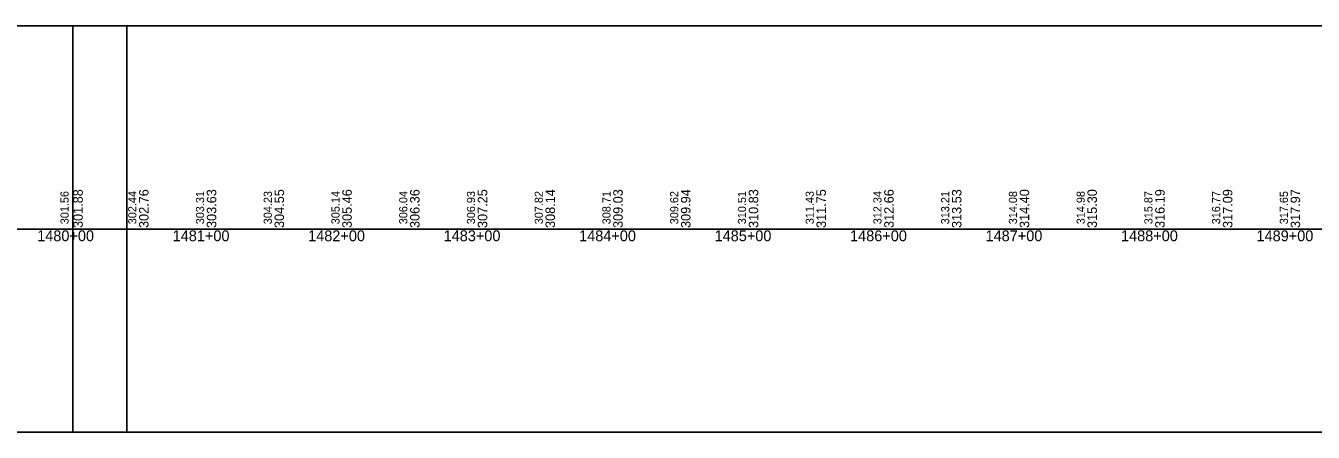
# Model space of a CAD drawing. Extents: x 2898 to 49495, y -15038 to -13538.
# Drawn here: x 37421 to 38371, y -15038 to -14738 of the extents above; entities that cross this region are included whole.
import ezdxf

# ---------------------------------------------------------------- set-up
doc = ezdxf.new("R2010")
doc.units = 0
for name, color, linetype in [('RD_DDB_StaTX', 7, 'Continuous'), ('RD_DDB_StripGrade', 7, 'Continuous'), ('RD_GPK_Profile_Cell', 7, 'Continuous'), ('RD_SHT_ShtClip', 7, 'Continuous')]:
    doc.layers.add(name, color=color, linetype=linetype)

msp = doc.modelspace()

# ---------------------------------------------------------------- linework, layer by layer
at = {"layer": 'RD_GPK_Profile_Cell'}
msp.add_line((2976.05, -14888.47), (48721.13, -14888.47), dxfattribs=at)
at = {"layer": 'RD_SHT_ShtClip'}
for points in [[(35955.38, -14738.47), (37495.38, -14738.47), (37495.38, -15038.47), (35955.38, -15038.47)], [(37455.38, -14738.47), (38995.38, -14738.47), (38995.38, -15038.47), (37455.38, -15038.47)]]:
    msp.add_lwpolyline(points, close=True, dxfattribs=at)

# ---------------------------------------------------------------- texts
at = {"layer": 'RD_DDB_StaTX'}
for s, p in [('1480+00', (37429.18, -14897.47)), ('1481+00', (37529.18, -14897.47)), ('1482+00', (37629.18, -14897.47)), ('1483+00', (37729.18, -14897.47)), ('1484+00', (37829.18, -14897.47)), ('1485+00', (37929.18, -14897.47)), ('1486+00', (38029.18, -14897.47)), ('1487+00', (38129.18, -14897.47)), ('1488+00', (38229.18, -14897.47)), ('1489+00', (38329.18, -14897.47))]:
    msp.add_text(s, height=8, dxfattribs=at).set_placement(p)
at = {"layer": 'RD_DDB_StripGrade'}
for s, height, p in [('301.56', 6, (37452.38, -14884.98)), ('301.88', 7, (37462.82, -14887.72)), ('302.44', 6, (37502.38, -14884.98)), ('302.76', 7, (37511.38, -14887.72)), ('303.31', 6, (37552.38, -14884.98)), ('303.63', 7, (37561.38, -14887.72)), ('304.23', 6, (37602.38, -14884.98)), ('304.55', 7, (37611.38, -14887.72)), ('305.14', 6, (37652.38, -14884.98)), ('305.46', 7, (37661.38, -14887.72)), ('306.04', 6, (37702.38, -14884.98)), ('306.36', 7, (37711.38, -14887.72)), ('306.93', 6, (37752.38, -14884.98)), ('307.25', 7, (37761.38, -14887.72)), ('307.82', 6, (37802.38, -14884.98)), ('308.14', 7, (37811.38, -14887.72)), ('308.71', 6, (37852.38, -14884.98)), ('309.03', 7, (37861.38, -14887.72)), ('309.62', 6, (37902.38, -14884.98)), ('309.94', 7, (37911.38, -14887.72)), ('310.51', 6, (37952.38, -14884.98)), ('310.83', 7, (37961.38, -14887.72)), ('311.43', 6, (38002.38, -14884.98)), ('311.75', 7, (38011.38, -14887.72)), ('312.34', 6, (38052.38, -14884.98)), ('312.66', 7, (38061.38, -14887.72)), ('313.21', 6, (38102.38, -14884.98)), ('313.53', 7, (38111.38, -14887.72)), ('314.08', 6, (38152.38, -14884.98)), ('314.40', 7, (38161.38, -14887.72)), ('314.98', 6, (38202.38, -14884.98)), ('315.30', 7, (38211.38, -14887.72)), ('315.87', 6, (38252.38, -14884.98)), ('316.19', 7, (38261.38, -14887.72)), ('316.77', 6, (38302.38, -14884.98)), ('317.09', 7, (38311.38, -14887.72)), ('317.65', 6, (38352.38, -14884.98)), ('317.97', 7, (38361.38, -14887.72))]:
    msp.add_text(s, height=height, rotation=90, dxfattribs=at).set_placement(p)

doc.saveas('drawing.dxf')
